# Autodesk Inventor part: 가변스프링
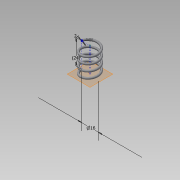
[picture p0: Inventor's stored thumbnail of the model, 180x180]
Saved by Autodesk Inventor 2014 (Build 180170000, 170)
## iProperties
Created: 2015-04
Part Number: 가변스프링
Material: Generic
Document SubType Name: Modeling
Designer: Administrator
Density: 1 g/cm^3
Appearance: Default
Mass: 0.582816 g
Surface Area: 12.8728 cm^2
Volume: 0.582816 cm^3
Author: Administrator
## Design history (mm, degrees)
sketch "스케치1"
  geometry: L1 (0, 0)-(-8, 0); L2 (-8, 0)-(-8, -11.5); L3 (-8, -11.5)-(0, -11.5); L4 (0, -11.5)-(0, 0); C1 r 1 at (-8, 0); 1 further point
  constraints: 8 end point, 2 coincident, 2 parallel, 1 centre point, 1 horizontal, 1 perpendicular
  dimensions: "d0" = 16 diameter of L2 L4; "d1" = 11.50049 distance between parallel lines of L3 L1 (derived); "d2" = 2 diameter of C1
feature "코일1" pitch "d3" = 10; turns "d5" = 4; dims "d4" = 11.50049 (= d1), "d6" = 0, angle "d7" = 90 deg, angle "d8" = 90 deg, "d9" = 0, "d10" = 0
sketch "스케치2"
  geometry: L1 (7, 0)-(9, 0) reference; 1 further point
  constraints: 1 horizontal alignment
extrude "돌출1" cut sketch "스케치2" stored distance "d11" = 10; taper "d12" = 0 deg
node "작업 평면1"
sketch "스케치3"
  geometry: L1 (9, 0)-(7, 0) reference; 1 further point
  constraints: 1 horizontal alignment
extrude "돌출2" cut sketch "스케치3" stored distance "d13" = 10; taper "d14" = 0 deg
node "솔리드1"
node "절단 모서리 투영1"
node "절단 모서리 투영2"
